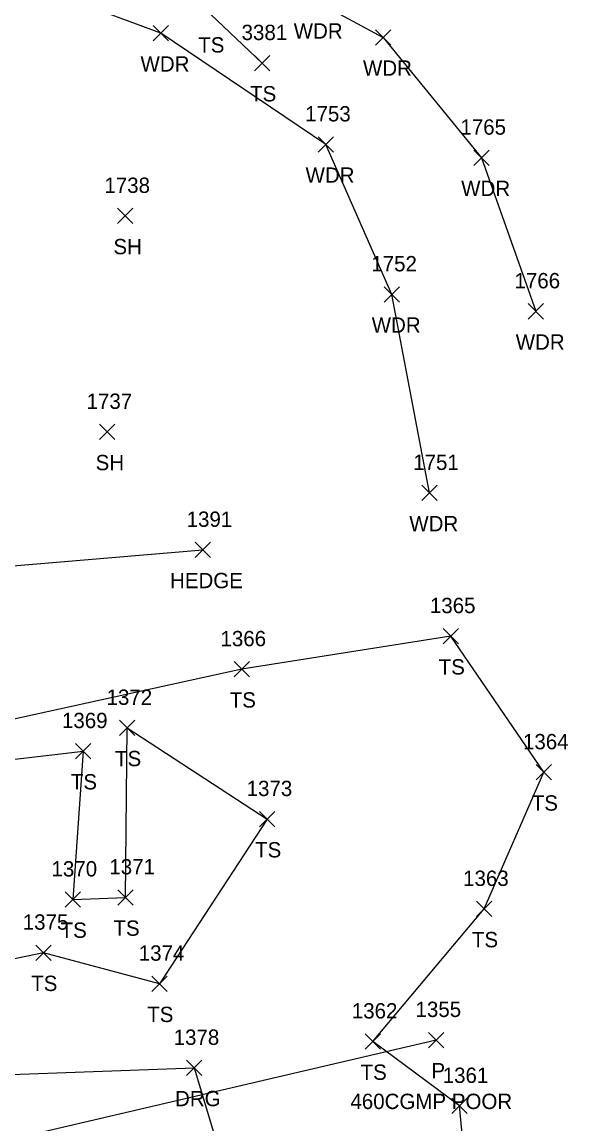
# Model space of a CAD drawing. Extents: x 462930 to 463548, y 29607 to 30453.
# Drawn here: x 463360 to 463381.72, y 30059.67 to 30103.46 of the extents above; entities that cross this region are included whole.
import ezdxf

# ---------------------------------------------------------------- set-up
doc = ezdxf.new("R2010")
doc.units = 0
for name, color, linetype in [('D_A', 7, 'Continuous'), ('D_C', 7, 'Continuous'), ('D_I', 7, 'Continuous'), ('D_TIC', 7, 'Continuous'), ('DCP', 7, 'Continuous'), ('L_A', 7, 'Continuous'), ('L_I', 7, 'Continuous'), ('L_TIC', 7, 'Continuous'), ('LAHR', 7, 'Continuous'), ('LAWA', 7, 'Continuous'), ('LELB', 7, 'Continuous'), ('R_A', 7, 'Continuous'), ('R_I', 7, 'Continuous'), ('R_TIC', 7, 'Continuous'), ('RDG', 7, 'Continuous')]:
    doc.layers.add(name, color=color, linetype=linetype)

msp = doc.modelspace()

# ---------------------------------------------------------------- linework, layer by layer
at = {"layer": 'D_TIC'}
for points in [[(463376.17, 30062.703), (463376.78, 30063.313)], [(463376.78, 30062.703), (463376.17, 30063.313)]]:
    msp.add_lwpolyline(points, dxfattribs=at)
at = {"layer": 'DCP'}
msp.add_lwpolyline([(463376.475, 30063.008), (463342.539, 30055.084)], dxfattribs=at)
at = {"layer": 'L_TIC'}
for points in [[(463365.215, 30102.71), (463365.825, 30103.32)], [(463365.825, 30102.71), (463365.215, 30103.32)], [(463374.063, 30102.544), (463374.673, 30103.154)], [(463374.673, 30102.544), (463374.063, 30103.154)], [(463369.253, 30101.524), (463369.862, 30102.133)], [(463369.862, 30101.524), (463369.253, 30102.133)], [(463371.78, 30098.291), (463372.39, 30098.901)], [(463372.39, 30098.291), (463371.78, 30098.901)], [(463377.969, 30097.764), (463378.579, 30098.374)], [(463378.579, 30097.764), (463377.969, 30098.374)], [(463363.796, 30095.45), (463364.406, 30096.06)], [(463364.406, 30095.45), (463363.796, 30096.06)], [(463374.411, 30092.333), (463375.021, 30092.943)], [(463375.021, 30092.333), (463374.411, 30092.943)], [(463380.138, 30091.659), (463380.748, 30092.269)], [(463380.748, 30091.659), (463380.138, 30092.269)], [(463363.088, 30086.868), (463363.698, 30087.478)], [(463363.698, 30086.868), (463363.088, 30087.478)], [(463375.905, 30084.441), (463376.515, 30085.051)], [(463376.515, 30084.441), (463375.905, 30085.051)], [(463366.895, 30082.181), (463367.505, 30082.791)], [(463367.505, 30082.181), (463366.895, 30082.791)], [(463376.756, 30078.751), (463377.366, 30079.361)], [(463377.366, 30078.751), (463376.756, 30079.361)], [(463368.444, 30077.436), (463369.054, 30078.046)], [(463369.054, 30077.436), (463368.444, 30078.046)], [(463363.883, 30075.107), (463364.493, 30075.717)], [(463364.493, 30075.107), (463363.883, 30075.717)], [(463362.126, 30074.183), (463362.736, 30074.793)], [(463362.736, 30074.183), (463362.126, 30074.793)], [(463380.458, 30073.341), (463381.068, 30073.951)], [(463381.068, 30073.341), (463380.458, 30073.951)], [(463369.454, 30071.482), (463370.064, 30072.092)], [(463370.064, 30071.482), (463369.454, 30072.092)], [(463361.719, 30068.287), (463362.329, 30068.897)], [(463362.329, 30068.287), (463361.719, 30068.897)], [(463363.82, 30068.368), (463364.43, 30068.978)], [(463364.43, 30068.368), (463363.82, 30068.978)], [(463378.076, 30067.911), (463378.686, 30068.521)], [(463378.686, 30067.911), (463378.076, 30068.521)], [(463360.549, 30066.173), (463361.159, 30066.783)], [(463361.159, 30066.173), (463360.549, 30066.783)], [(463365.163, 30064.94), (463365.773, 30065.55)], [(463365.773, 30064.94), (463365.163, 30065.55)], [(463373.65, 30062.644), (463374.26, 30063.254)], [(463374.26, 30062.644), (463373.65, 30063.254)], [(463377.092, 30060.083), (463377.702, 30060.693)], [(463377.702, 30060.083), (463377.092, 30060.693)]]:
    msp.add_lwpolyline(points, dxfattribs=at)
at = {"layer": 'LAHR'}
msp.add_lwpolyline([(463358.065, 30081.719), (463367.2, 30082.486)], dxfattribs=at)
at = {"layer": 'LAWA'}
for points in [[(463376.21, 30084.746), (463374.716, 30092.638), (463372.085, 30098.596), (463365.52, 30103.015), (463354.967, 30106.923), (463349.945, 30110.993), (463346.764, 30113.257)], [(463371.613, 30104.325), (463374.368, 30102.849)], [(463374.368, 30102.849), (463378.274, 30098.069), (463380.443, 30091.964)]]:
    msp.add_lwpolyline(points, dxfattribs=at)
at = {"layer": 'LELB'}
for points in [[(463343.625, 30116.989), (463343.551, 30115.889), (463346.121, 30115.132), (463348.213, 30115.888), (463350.835, 30113.965), (463354.177, 30110.301), (463358.469, 30108.098), (463361.951, 30106.722), (463364.431, 30105.371), (463367.498, 30103.77), (463369.557, 30101.829)], [(463378.516, 30048.648), (463377.397, 30060.388), (463373.955, 30062.949), (463378.381, 30068.216), (463380.763, 30073.646), (463377.061, 30079.056), (463368.749, 30077.741), (463357.917, 30075.38), (463358.238, 30073.999), (463362.431, 30074.488), (463362.024, 30068.592), (463364.125, 30068.673), (463364.188, 30075.412), (463369.759, 30071.787), (463365.468, 30065.245), (463360.854, 30066.478), (463353.772, 30065.008)]]:
    msp.add_lwpolyline(points, dxfattribs=at)
at = {"layer": 'R_TIC'}
for points in [[(463366.551, 30061.596), (463367.161, 30062.206)], [(463367.161, 30061.596), (463366.551, 30062.206)]]:
    msp.add_lwpolyline(points, dxfattribs=at)
at = {"layer": 'RDG'}
msp.add_lwpolyline([(463355.188, 30061.475), (463366.856, 30061.901), (463368.547, 30056.261), (463358.377, 30057.19)], dxfattribs=at)

# ---------------------------------------------------------------- texts
at = {"layer": 'D_A'}
msp.add_text('P', height=0.61, dxfattribs=at).set_placement((463376.285, 30061.484))
at = {"layer": 'D_C'}
msp.add_text('460CGMP POOR', height=0.6096, dxfattribs=at).set_placement((463373.065, 30060.265))
at = {"layer": 'D_I'}
msp.add_text('1355', height=0.6096, dxfattribs=at).set_placement((463375.654, 30063.922))
at = {"layer": 'L_A'}
for s, p in [('WDR', (463370.809, 30102.801)), ('TS', (463367.013, 30102.246)), ('WDR', (463364.716, 30101.491)), ('WDR', (463373.564, 30101.325)), ('TS', (463369.073, 30100.305)), ('WDR', (463371.281, 30097.072)), ('WDR', (463377.47, 30096.545)), ('SH', (463363.64, 30094.231)), ('WDR', (463373.912, 30091.114)), ('WDR', (463379.639, 30090.44)), ('SH', (463362.932, 30085.649)), ('WDR', (463375.406, 30083.222)), ('HEDGE', (463365.89, 30080.962)), ('TS', (463376.576, 30077.532)), ('TS', (463368.264, 30076.217)), ('TS', (463363.703, 30073.888)), ('TS', (463361.946, 30072.964)), ('TS', (463380.278, 30072.122)), ('TS', (463369.274, 30070.263)), ('TS', (463361.539, 30067.068)), ('TS', (463363.64, 30067.149)), ('TS', (463377.896, 30066.692)), ('TS', (463360.369, 30064.954)), ('TS', (463364.983, 30063.721)), ('TS', (463373.47, 30061.425))]:
    msp.add_text(s, height=0.6096, dxfattribs=at).set_placement(p)
at = {"layer": 'L_I'}
for s, p in [('3381', (463368.737, 30102.743)), ('1753', (463371.264, 30099.51)), ('1765', (463377.439, 30098.983)), ('1738', (463363.28, 30096.669)), ('1752', (463373.895, 30093.552)), ('1766', (463379.591, 30092.878)), ('1737', (463362.572, 30088.087)), ('1751', (463375.562, 30085.66)), ('1391', (463366.552, 30083.4)), ('1365', (463376.226, 30079.97)), ('1366', (463367.897, 30078.655)), ('1372', (463363.367, 30076.326)), ('1369', (463361.593, 30075.402)), ('1364', (463379.928, 30074.56)), ('1373', (463368.938, 30072.701)), ('1370', (463361.177, 30069.506)), ('1371', (463363.477, 30069.587)), ('1363', (463377.546, 30069.13)), ('1375', (463360.033, 30067.392)), ('1374', (463364.647, 30066.159)), ('1362', (463373.12, 30063.863)), ('1361', (463376.735, 30061.302))]:
    msp.add_text(s, height=0.6096, dxfattribs=at).set_placement(p)
at = {"layer": 'R_A'}
msp.add_text('DRG', height=0.6096, dxfattribs=at).set_placement((463366.09, 30060.377))
at = {"layer": 'R_I'}
msp.add_text('1378', height=0.6096, dxfattribs=at).set_placement((463366.035, 30062.815))

doc.saveas('drawing.dxf')
